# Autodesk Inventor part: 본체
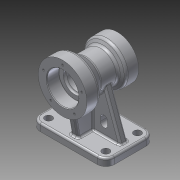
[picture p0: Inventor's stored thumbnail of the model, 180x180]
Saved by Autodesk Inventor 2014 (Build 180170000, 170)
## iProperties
Created: 2015-08
Part Number: 본체
Material: 알루미늄 6061
Document SubType Name: Modeling
Designer: Owner
Density: 2.71 g/cm^3
Appearance: 알루미늄 - 평지
Mass: 1062.79 g
Surface Area: 749.652 cm^2
Volume: 392.172 cm^3
Author: Owner
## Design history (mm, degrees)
sketch "스케치1"
  geometry: L1 (-61, 40)-(61, 40); L2 (61, 40)-(61, -40); L3 (61, -40)-(-61, -40); L4 (-61, -40)-(-61, 40); L5 (-61, 40)-(61, -40); L6 (61, 40)-(-61, -40); 3 further points
  constraints: 12 end point, 3 midpoint, 2 parallel, 1 coincident, 1 horizontal, 1 perpendicular
  dimensions: "d0" = 122 distance of L2.end L3.end; "d1" = 80 distance between parallel lines of L1 L3
extrude "돌출1" new body sketch "스케치1" distance "d2" = 12; taper "d3" = 0 deg
sketch "스케치2"
  geometry: L1 (116, 50)-(116, 30); L2 (116, 30)-(109, 30); L3 (106, 27)-(106, -23); L4 (106, -23)-(110, -23); L5 (110, -23)-(110, -40); L6 (110, -40)-(125, -40); L7 (125, -40)-(125, -20); L8 (125, -20)-(116, -14.804); L9 (116, -14.804)-(116, 13.315); L10 (116, 13.315)-(130, 30); L11 (130, 30)-(130, 50); L12 (130, 50)-(116, 50); L13 (90, -40)-(90, 40); L14 (0, 40)-(12, 40) reference; L15 (0, -40)-(12, -40) reference; A1 r 3 centre (106, 30) between (106, 27) and (109, 30); 1 further point
  constraints: 26 end point, 5 parallel, 5 perpendicular, 4 point on line, 2 point on circle, 1 centre point, 1 collinear, 1 vertical
  dimensions: "d4" = 90 distance from line of L13 point (0, 0); "d5" = 16 distance between parallel lines of L13 L3; "d6" = 26 distance between parallel lines of L13 L1; "d7" = 3 radius of A1; "d8" = 19 distance from line of L13 L2.end (derived); "d9" = 20 distance between parallel lines of L13 L5; "d10" = 35 distance between parallel lines of L13 L7; "d11" = 40 distance between parallel lines of L13 L11; "d12" = 17 distance of L4.end L5.end; "d13" = 90 distance between parallel lines of L12 L6; "d14" = 20 distance of L10.end L11.end; "d15" = 20 distance of L6.end L7.end; "d16" = 40 deg angle of L9 L10; "d17" = 60 deg angle of L9 L8; "d18" = 26 distance between parallel lines of L13 L9; "d19" = 20 distance between parallel lines of L2 L12
revolve "회전1" sketch "스케치2" stored, may be unused: angle "d20" = 90 deg
sketch "스케치3"
  geometry: 5 further points
  constraints: 2 horizontal alignment, 2 vertical alignment
  dimensions: "d21" = 47 horizontal distance of point (0, 0) point (-47, 26); "d22" = 26 vertical distance of point (0, 0) point (-47, 26); "d23" = 26 vertical distance of point (0, 0) point (-47, -26); "d24" = 47 horizontal distance of point (0, 0) point (47, 26)
hole "구멍1" sketch "스케치3" at (-47, 26), (47, 26), (-47, -26), (47, -26) diameter "d25" = 12; stored, may be unused: countersink angle "d29" = 90 deg, drill point angle "d31" = 118 deg; dims "d26" = 6, "d27" = 4, "d28" = 2, "d30" = 8
fillet "모깎기1" dims "d32" = 14
sketch "스케치4"
  geometry: L1 (12, 40)-(12, 26) reference; L2 (12, -26)-(12, -40) reference; L3 (0, 40)-(12, 40) reference; L4 (12, -40)-(0, -40) reference; L5 (50, 50)-(50, 30) reference; L6 (55, -20)-(55, -40) reference; L7 (12, -30)-(62, -30); L8 (12, 30)-(57, 37.935); 1 further point
  constraints: 4 end point, 2 point on line, 1 perpendicular
  dimensions: "d42" = 45 horizontal distance of L8.start L8.end; "d43" = 50 distance of L7.start L7.end; "d44" = 10 distance from line of L4 L7.start; "d45" = 10 distance from line of L3 L8.start; "d46" = 80 deg angle of L1 L8
sketch "스케치5"
  geometry: L1 (-51, 12)-(-25.091, 83.185); L2 (-61, 12)-(-47, 12) reference; L3 (-61, 0)-(-61, 12) reference; L4 (51, 12)-(25.091, 83.185); L5 (61, 12)-(61, 0) reference; L6 (47, 12)-(61, 12) reference; A1 r 26 centre (0, 90) between (25.091, 83.185) and (-25.091, 83.185) reference; 1 further point
  constraints: 4 end point, 2 point on circle, 2 point on line
  dimensions: "d38" = 10 distance from line of L3 L1.start; "d39" = 70 deg angle of L2 L1; "d40" = 10 distance from line of L5 L4.start; "d41" = 70 deg angle of L6 L4
feature "리브1" dims "d47" = 1, "d48" = 6, "d49" = 0, "d50" = 0, "d51" = 1, "d52" = 1
feature "리브2" dims "d53" = 1, "d54" = 6, "d55" = 0, "d56" = 0, "d57" = 1, "d58" = 1
feature "리브3" dims "d59" = 1, "d60" = 12, "d61" = 0, "d62" = 0, "d63" = 1, "d64" = 1
feature "리브4" dims "d65" = 1, "d66" = 12, "d67" = 0, "d68" = 0, "d69" = 1, "d70" = 1
sketch "스케치6" dims "d71" = 66
  geometry: C1 r 26 at (0, 0) reference; C2 r 40 at (0, 0) reference; 7 further points
  constraints: 2 vertical alignment, 1 coincident, 8 other
  dimensions: "d74" = 360 deg dimension on C1.centre point (0, 33) (derived)
hole "구멍2" sketch "스케치6" at (0, 33), (-31.385, 10.198), (-19.397, -26.698), (19.397, -26.698), (31.385, 10.198) diameter "d76" = 3.242; stored, may be unused: countersink angle "d80" = 90 deg, drill point angle "d82" = 118 deg; dims "d77" = 10, "d78" = 4, "d79" = 2, "d81" = 13
sketch "스케치7" dims "d83" = 54
  geometry: C1 r 35 at (0, 0) reference; C2 r 20 at (0, 0) reference; 7 further points
  constraints: 2 vertical alignment, 1 coincident, 8 other
  dimensions: "d86" = 360 deg dimension on C1.centre point (0, 27) (derived)
hole "구멍3" sketch "스케치7" at (0, 27), (-25.679, 8.343), (-15.87, -21.843), (15.87, -21.843), (25.679, 8.343) diameter "d88" = 3.242; stored, may be unused: countersink angle "d92" = 90 deg, drill point angle "d94" = 118 deg; dims "d89" = 10, "d90" = 4, "d91" = 2, "d93" = 13
fillet "모깎기2" dims "d95" = 0.3
fillet "모깎기3" dims "d96" = 5
fillet "모깎기4" dims "d97" = 3
fillet "모깎기5" dims "d98" = 3
fillet "모깎기6" dims "d99" = 3
fillet "모깎기7" dims "d100" = 3
fillet "모깎기8" dims "d101" = 3
fillet "모깎기9" dims "d102" = 3
fillet "모깎기10" dims "d103" = 3
fillet "모깎기11" dims "d104" = 3
chamfer "모따기1" distance "d105" = 1; stored, may be unused: second distance "d106" = 2, angle "d107" = 45 deg
sketch "스케치8"
  geometry: L1 (-13, -15)-(-13, -6) reference; L2 (-10, -3)-(1, -3) reference; 2 further points
  constraints: 1 other
  dimensions: "d108" = 26 distance from line of point (13, 21) L1; "d109" = 24 distance from line of point (13, 21) L2
feature "엠보싱1" sketch "스케치8" dims "d0" = 122, "d1" = 80, "d110" = 0.5, "d111" = 0
sketch "스케치9"
  geometry: L1 (28.716, 15)-(16.716, 15); L2 (16.716, 15)-(16.716, 21); L3 (16.716, 21)-(28.716, 21); L4 (28.716, 21)-(28.716, 15); L5 (-0.284, -6)-(93.716, -6) reference; L6 (-11.284, -3)-(-0.284, -3) reference; A1 r 6 centre (22.716, 15) between (16.716, 15) and (28.716, 15); A2 r 6 centre (22.716, 21) between (28.716, 21) and (16.716, 21); 1 further point
  constraints: 8 end point, 4 point on circle, 2 centre point, 2 midpoint, 2 parallel, 1 horizontal, 1 perpendicular
  dimensions: "d113" = 24 horizontal distance of point (46.716, -15) A1.centre; "d114" = 12 distance between parallel lines of L4 L2; "d115" = 6 distance of A2.centre A1.centre; "d118" = 18 distance from line of L6 A1.centre
extrude "돌출2" cut sketch "스케치9" stored distance "d116" = 10; taper "d117" = 0 deg
node "솔리드1"
mirror "대칭1"
